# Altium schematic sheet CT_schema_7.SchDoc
size 296 x 239 mm
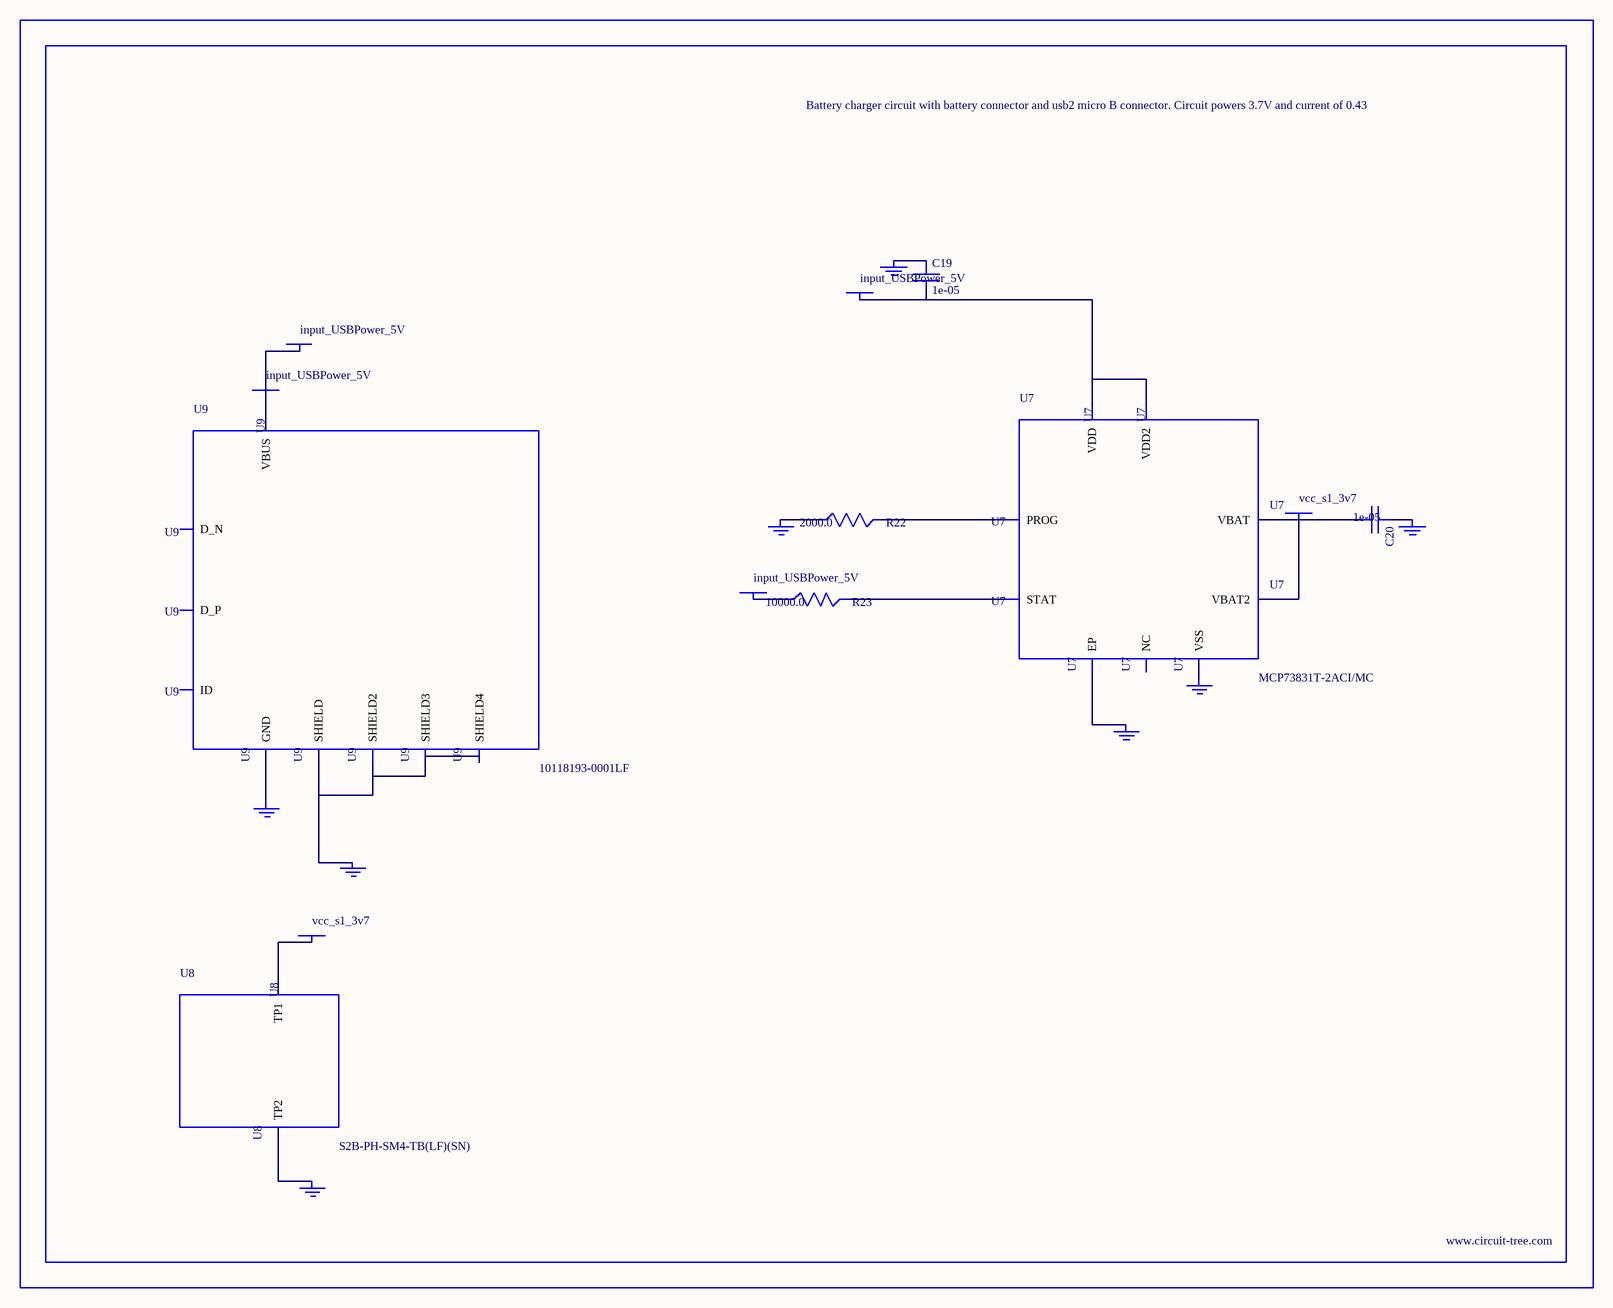
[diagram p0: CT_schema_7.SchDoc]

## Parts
BORDER6  (no value)
C19  1e-05  [C1206]
C20  1e-05  [C1206]
GND_INSTANCE_6_0  (no value)
GND_INSTANCE_6_1  (no value)
GND_INSTANCE_6_2  (no value)
GND_INSTANCE_6_3  (no value)
GND_INSTANCE_6_4  (no value)
GND_INSTANCE_6_5  (no value)
GND_INSTANCE_6_6  (no value)
GND_INSTANCE_6_7  (no value)
POWER_INSTANCE_6_0  input_USBPower_5V
POWER_INSTANCE_6_1  input_USBPower_5V
POWER_INSTANCE_6_2  vcc_s1_3v7
POWER_INSTANCE_6_3  vcc_s1_3v7
POWER_INSTANCE_6_4  input_USBPower_5V
POWER_INSTANCE_6_5  input_USBPower_5V
R22  2000.0  [R0603]
R23  10000.0  [R0603]
U7  MCP73831T-2ACI/MC  [DFN8_2X3MC]
U8  S2B-PH-SM4-TB(LF)(SN)  [JST-2-SMD]
U9  10118193-0001LF  [FCI_10118193-0001LF]

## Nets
NetC19_1: C19.1 GND_INSTANCE_6_0.0(GND)
NetC19_2: C19.2 POWER_INSTANCE_6_0.0(PWR) U7.1(VDD) U7.2(VDD2)
NetC20_1: C20.1 GND_INSTANCE_6_1.0(GND)
NetC20_2: C20.2 POWER_INSTANCE_6_2.0(PWR) U7.3(VBAT) U7.4(VBAT2)
NetGND_INSTANCE_6_2_0: GND_INSTANCE_6_2.0(GND) R22.1
NetGND_INSTANCE_6_3_0: GND_INSTANCE_6_3.0(GND) U7.9(EP)
NetGND_INSTANCE_6_4_0: GND_INSTANCE_6_4.0(GND) U7.6(VSS)
NetGND_INSTANCE_6_5_0: GND_INSTANCE_6_5.0(GND) U8.2(TP2)
NetGND_INSTANCE_6_6_0: GND_INSTANCE_6_6.0(GND) U9.6(SHIELD) U9.7(SHIELD2) U9.8(SHIELD3) U9.9(SHIELD4)
NetGND_INSTANCE_6_7_0: GND_INSTANCE_6_7.0(GND) U9.5(GND)
NetPOWER_INSTANCE_6_1_0: POWER_INSTANCE_6_1.0(PWR) R23.1
NetPOWER_INSTANCE_6_3_0: POWER_INSTANCE_6_3.0(PWR) U8.1(TP1)
NetPOWER_INSTANCE_6_4_0: POWER_INSTANCE_6_4.0(PWR) POWER_INSTANCE_6_5.0(PWR) U9.1(VBUS)
NetR22_2: R22.2 U7.8(PROG)
NetR23_2: R23.2 U7.5(STAT)

Not connected (* = marked no-connect by the designer): U7 7(NC); U9 2(D_N) 3(D_P) 4(ID)

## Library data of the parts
BORDER6 = BORDER_PAGE6
C19 C20 = C1206C106K3RACTU
GND_INSTANCE_6_0-GND_INSTANCE_6_7 = GND
POWER_INSTANCE_6_0-POWER_INSTANCE_6_5 = PWR
R22 = RC0603JR-072KL
R23 = RC0603JR-0710KL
